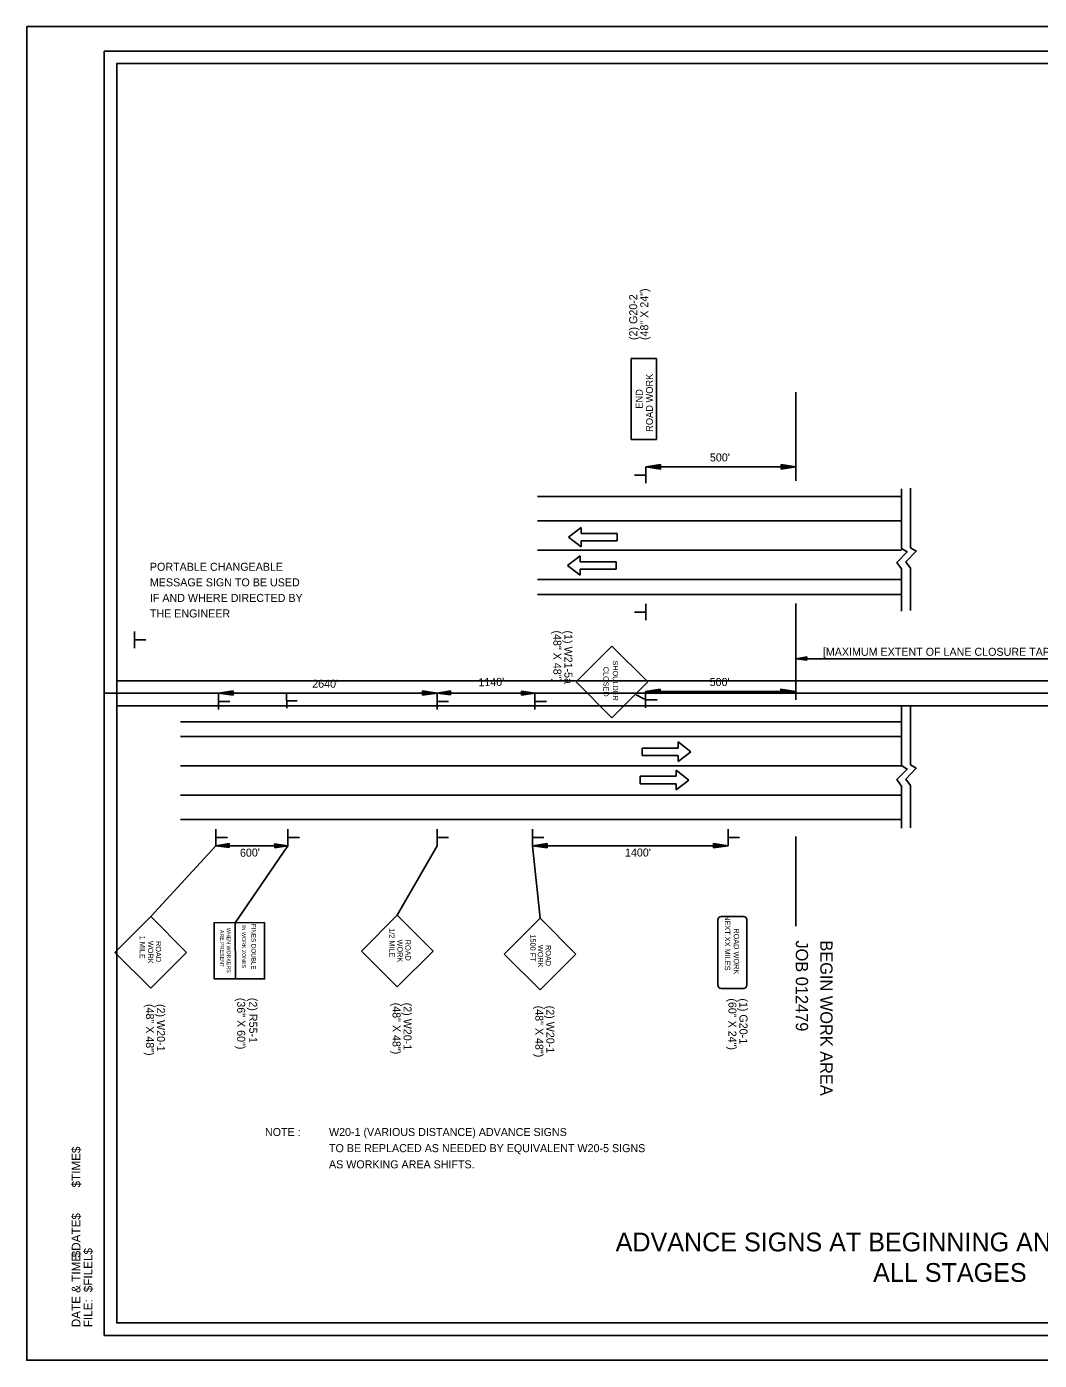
# Model space of a CAD drawing. Extents: x 1373222 to 1374279, y 380783 to 380996.
# Drawn here: x 1373222 to 1373384, y 380783.1 to 380996.5 of the extents above; entities that cross this region are included whole.
import ezdxf

# ---------------------------------------------------------------- set-up
doc = ezdxf.new("R2010")
doc.units = 0
for name, color, linetype in [('R_Border', 7, 'Continuous'), ('R_Border Notes', 7, 'Continuous'), ('R_Border Plan-Plan', 7, 'Continuous'), ('R_Draft', 7, 'Continuous'), ('R_No Plot', 7, 'Continuous')]:
    doc.layers.add(name, color=color, linetype=linetype)

msp = doc.modelspace()

# ---------------------------------------------------------------- linework, layer by layer
at = {"layer": 'R_Border'}
for p, q in [((1373234.38, 380992.59), (1373550.56, 380992.59)), ((1373234.38, 380787.13), (1373234.38, 380992.59)), ((1373234.38, 380787.13), (1373234.38, 380787.13)), ((1373550.56, 380787.13), (1373234.38, 380787.13))]:
    msp.add_line(p, q, dxfattribs=at)
at = {"layer": 'R_Border Plan-Plan'}
msp.add_line((1373234.38, 380889.86), (1373550.56, 380889.86), dxfattribs=at)
at = {"layer": 'R_Draft'}
for p, q in [((1373318.66, 380943.42), (1373318.66, 380930.43)), ((1373322.74, 380943.42), (1373318.66, 380943.42)), ((1373322.74, 380943.42), (1373322.74, 380930.43)), ((1373345.02, 380923.82), (1373345.02, 380938)), ((1373322.74, 380930.43), (1373318.66, 380930.43)), ((1373323.38, 380926.44), (1373321.03, 380926.08)), ((1373321.03, 380923.44), (1373321.03, 380926.08)), ((1373345.02, 380926.08), (1373321.03, 380926.08)), ((1373323.38, 380925.73), (1373321.03, 380926.08)), ((1373323.38, 380926.38), (1373321.42, 380926.08)), ((1373323.38, 380925.79), (1373321.42, 380926.08)), ((1373323.38, 380926.32), (1373321.83, 380926.08)), ((1373323.38, 380925.85), (1373321.83, 380926.08)), ((1373323.38, 380926.26), (1373322.22, 380926.08)), ((1373323.38, 380925.91), (1373322.22, 380926.08)), ((1373323.38, 380926.2), (1373322.61, 380926.08)), ((1373323.38, 380925.97), (1373322.61, 380926.08)), ((1373323.38, 380926.14), (1373323.01, 380926.08)), ((1373323.38, 380926.03), (1373323.01, 380926.08)), ((1373323.38, 380925.73), (1373323.38, 380926.44)), ((1373342.68, 380926.44), (1373345.02, 380926.08)), ((1373342.68, 380926.44), (1373342.68, 380925.73)), ((1373342.68, 380926.38), (1373344.63, 380926.08)), ((1373342.68, 380926.32), (1373344.23, 380926.08)), ((1373342.68, 380926.26), (1373343.84, 380926.08)), ((1373342.68, 380926.2), (1373343.44, 380926.08)), ((1373342.68, 380926.14), (1373343.05, 380926.08)), ((1373342.68, 380925.73), (1373345.02, 380926.08)), ((1373342.68, 380925.97), (1373343.44, 380926.08)), ((1373342.68, 380925.85), (1373344.23, 380926.08)), ((1373342.68, 380925.79), (1373344.63, 380926.08)), ((1373342.68, 380925.91), (1373343.84, 380926.08)), ((1373342.68, 380926.03), (1373343.05, 380926.08)), ((1373320.99, 380924.76), (1373319.19, 380924.76)), ((1373303.69, 380921.33), (1373361.91, 380921.33)), ((1373361.91, 380913.03), (1373361.91, 380922.56)), ((1373363.36, 380913.14), (1373363.36, 380922.67)), ((1373303.69, 380917.42), (1373361.91, 380917.42)), ((1373308.64, 380914.83), (1373310.67, 380916.39)), ((1373310.67, 380913.26), (1373308.64, 380914.83)), ((1373310.67, 380915.41), (1373310.67, 380916.39)), ((1373310.67, 380915.41), (1373316.43, 380915.41)), ((1373316.43, 380914.24), (1373316.43, 380915.41)), ((1373303.69, 380912.72), (1373361.91, 380912.72)), ((1373310.67, 380914.24), (1373316.43, 380914.24)), ((1373310.67, 380913.26), (1373310.67, 380914.24)), ((1373308.49, 380910.29), (1373310.52, 380911.86)), ((1373310.52, 380908.73), (1373308.49, 380910.29)), ((1373310.52, 380910.88), (1373310.52, 380911.86)), ((1373310.52, 380910.88), (1373316.28, 380910.88)), ((1373316.28, 380909.71), (1373316.28, 380910.88)), ((1373303.69, 380908.03), (1373361.91, 380908.03)), ((1373310.52, 380909.71), (1373316.28, 380909.71)), ((1373310.52, 380908.73), (1373310.52, 380909.71)), ((1373361.91, 380902.99), (1373361.91, 380909.74)), ((1373363.36, 380903.09), (1373363.36, 380909.85)), ((1373303.69, 380905.68), (1373361.91, 380905.68)), ((1373321.03, 380901.54), (1373321.03, 380904.18)), ((1373345.02, 380888.83), (1373345.02, 380904.23)), ((1373320.99, 380902.85), (1373319.19, 380902.85)), ((1373239.21, 380897.07), (1373239.21, 380899.71)), ((1373239.25, 380898.38), (1373241.05, 380898.38)), ((1373309.88, 380891.66), (1373315.61, 380897.39)), ((1373321.34, 380891.66), (1373315.61, 380897.39)), ((1373346.8, 380895.66), (1373345.02, 380895.39)), ((1373405.44, 380895.39), (1373345.02, 380895.39)), ((1373346.8, 380895.13), (1373345.02, 380895.39)), ((1373346.8, 380895.62), (1373345.32, 380895.39)), ((1373346.8, 380895.17), (1373345.32, 380895.39)), ((1373346.8, 380895.57), (1373345.63, 380895.39)), ((1373346.8, 380895.22), (1373345.63, 380895.39)), ((1373346.8, 380895.53), (1373345.92, 380895.39)), ((1373346.8, 380895.26), (1373345.92, 380895.39)), ((1373346.8, 380895.48), (1373346.23, 380895.39)), ((1373346.8, 380895.31), (1373346.23, 380895.39)), ((1373346.8, 380895.44), (1373346.52, 380895.39)), ((1373346.8, 380895.35), (1373346.52, 380895.39)), ((1373346.8, 380895.13), (1373346.8, 380895.66)), ((1373315.61, 380885.92), (1373309.88, 380891.66)), ((1373315.61, 380885.92), (1373321.34, 380891.66)), ((1373254.99, 380890.23), (1373252.64, 380889.88)), ((1373252.64, 380887.24), (1373252.64, 380889.88)), ((1373287.64, 380889.88), (1373252.64, 380889.88)), ((1373254.99, 380889.53), (1373252.64, 380889.88)), ((1373254.99, 380890.17), (1373253.03, 380889.88)), ((1373254.99, 380889.59), (1373253.03, 380889.88)), ((1373254.99, 380890.11), (1373253.44, 380889.88)), ((1373254.99, 380889.65), (1373253.44, 380889.88)), ((1373254.99, 380890.06), (1373253.83, 380889.88)), ((1373254.99, 380889.71), (1373253.83, 380889.88)), ((1373254.99, 380890), (1373254.22, 380889.88)), ((1373254.99, 380889.77), (1373254.22, 380889.88)), ((1373254.99, 380889.94), (1373254.62, 380889.88)), ((1373254.99, 380889.83), (1373254.62, 380889.88)), ((1373254.99, 380889.53), (1373254.99, 380890.23)), ((1373263.58, 380887.45), (1373263.54, 380889.85)), ((1373285.3, 380890.23), (1373287.64, 380889.88)), ((1373285.3, 380890.23), (1373285.3, 380889.53)), ((1373285.3, 380890.17), (1373287.25, 380889.88)), ((1373285.3, 380890.11), (1373286.85, 380889.88)), ((1373285.3, 380890.06), (1373286.46, 380889.88)), ((1373285.3, 380890), (1373286.06, 380889.88)), ((1373285.3, 380889.94), (1373285.67, 380889.88)), ((1373285.3, 380889.53), (1373287.64, 380889.88)), ((1373285.3, 380889.77), (1373286.06, 380889.88)), ((1373285.3, 380889.65), (1373286.85, 380889.88)), ((1373285.3, 380889.59), (1373287.25, 380889.88)), ((1373285.3, 380889.71), (1373286.46, 380889.88)), ((1373285.3, 380889.83), (1373285.67, 380889.88)), ((1373289.77, 380890.24), (1373287.64, 380889.88)), ((1373287.64, 380887.24), (1373287.64, 380889.88)), ((1373303.29, 380889.88), (1373287.64, 380889.88)), ((1373289.78, 380889.6), (1373287.64, 380889.88)), ((1373289.77, 380890.18), (1373288, 380889.89)), ((1373289.78, 380889.65), (1373288, 380889.89)), ((1373289.77, 380890.13), (1373288.37, 380889.89)), ((1373289.78, 380889.7), (1373288.37, 380889.89)), ((1373289.77, 380890.07), (1373288.72, 380889.9)), ((1373289.78, 380889.76), (1373288.72, 380889.9)), ((1373289.78, 380890.02), (1373289.08, 380889.9)), ((1373289.78, 380889.81), (1373289.08, 380889.9)), ((1373289.78, 380889.96), (1373289.44, 380889.91)), ((1373289.78, 380889.87), (1373289.44, 380889.91)), ((1373289.78, 380889.6), (1373289.77, 380890.24)), ((1373301.15, 380890.17), (1373303.29, 380889.88)), ((1373301.15, 380890.17), (1373301.16, 380889.53)), ((1373301.15, 380890.11), (1373302.93, 380889.88)), ((1373301.15, 380890.06), (1373302.57, 380889.87)), ((1373301.15, 380890.01), (1373302.21, 380889.86)), ((1373301.16, 380889.95), (1373301.85, 380889.86)), ((1373301.16, 380889.9), (1373301.49, 380889.85)), ((1373301.16, 380889.53), (1373303.29, 380889.88)), ((1373301.16, 380889.58), (1373302.93, 380889.88)), ((1373301.16, 380889.64), (1373302.57, 380889.87)), ((1373301.16, 380889.74), (1373301.85, 380889.86)), ((1373301.16, 380889.69), (1373302.21, 380889.86)), ((1373301.16, 380889.8), (1373301.49, 380889.85)), ((1373303.29, 380887.24), (1373303.29, 380889.88)), ((1373320.82, 380888.92), (1373319.47, 380889.61)), ((1373323.34, 380890.51), (1373320.99, 380890.16)), ((1373320.99, 380887.52), (1373320.99, 380890.16)), ((1373344.99, 380890.16), (1373320.99, 380890.16)), ((1373323.34, 380889.81), (1373320.99, 380890.16)), ((1373321.03, 380888.83), (1373322.83, 380888.83)), ((1373323.34, 380890.45), (1373321.38, 380890.16)), ((1373323.34, 380889.87), (1373321.38, 380890.16)), ((1373323.34, 380890.39), (1373321.79, 380890.16)), ((1373323.34, 380889.93), (1373321.79, 380890.16)), ((1373323.34, 380890.33), (1373322.18, 380890.16)), ((1373323.34, 380889.99), (1373322.18, 380890.16)), ((1373323.34, 380890.28), (1373322.58, 380890.16)), ((1373323.34, 380890.05), (1373322.58, 380890.16)), ((1373323.34, 380890.22), (1373322.97, 380890.16)), ((1373323.34, 380890.11), (1373322.97, 380890.16)), ((1373323.34, 380889.81), (1373323.34, 380890.51)), ((1373342.64, 380890.51), (1373344.99, 380890.16)), ((1373342.64, 380890.51), (1373342.64, 380889.81)), ((1373342.64, 380890.45), (1373344.59, 380890.16)), ((1373342.64, 380890.39), (1373344.19, 380890.16)), ((1373342.64, 380890.33), (1373343.8, 380890.16)), ((1373342.64, 380890.27), (1373343.4, 380890.16)), ((1373342.64, 380890.22), (1373343.01, 380890.16)), ((1373342.64, 380889.81), (1373344.99, 380890.16)), ((1373342.64, 380890.04), (1373343.4, 380890.16)), ((1373342.64, 380889.93), (1373344.19, 380890.16)), ((1373342.64, 380889.87), (1373344.59, 380890.16)), ((1373342.64, 380889.99), (1373343.8, 380890.16)), ((1373342.64, 380890.11), (1373343.01, 380890.16)), ((1373252.68, 380888.55), (1373254.48, 380888.55)), ((1373263.6, 380888.64), (1373265.23, 380888.67)), ((1373287.68, 380888.55), (1373289.48, 380888.55)), ((1373303.33, 380888.55), (1373305.13, 380888.55)), ((1373361.91, 380878.3), (1373361.91, 380887.82)), ((1373363.36, 380878.4), (1373363.36, 380887.92)), ((1373246.61, 380885.31), (1373342.65, 380885.31)), ((1373342.65, 380885.31), (1373361.91, 380885.31)), ((1373246.61, 380882.96), (1373342.65, 380882.96)), ((1373342.65, 380882.96), (1373361.91, 380882.96)), ((1373326.18, 380881.1), (1373320.43, 380881.1)), ((1373320.43, 380881.1), (1373320.43, 380879.92)), ((1373326.18, 380882.08), (1373326.18, 380881.1)), ((1373326.18, 380882.08), (1373328.21, 380880.51)), ((1373328.21, 380880.51), (1373326.18, 380878.95)), ((1373246.61, 380878.26), (1373342.65, 380878.26)), ((1373326.18, 380879.92), (1373320.43, 380879.92)), ((1373326.18, 380879.92), (1373326.18, 380878.95)), ((1373342.65, 380878.26), (1373361.96, 380878.26)), ((1373325.88, 380876.57), (1373320.13, 380876.57)), ((1373320.13, 380876.57), (1373320.13, 380875.39)), ((1373325.88, 380877.54), (1373325.88, 380876.57)), ((1373325.88, 380877.54), (1373327.91, 380875.98)), ((1373327.91, 380875.98), (1373325.88, 380874.41)), ((1373325.88, 380875.39), (1373320.13, 380875.39)), ((1373325.88, 380875.39), (1373325.88, 380874.41)), ((1373361.91, 380868.25), (1373361.91, 380875)), ((1373363.36, 380868.35), (1373363.36, 380875.11)), ((1373246.61, 380873.57), (1373342.65, 380873.57)), ((1373342.65, 380873.57), (1373361.91, 380873.57)), ((1373246.61, 380869.66), (1373342.65, 380869.66)), ((1373342.65, 380869.66), (1373361.91, 380869.66)), ((1373252.24, 380865.47), (1373252.24, 380868.11)), ((1373263.78, 380865.47), (1373263.78, 380868.11)), ((1373287.64, 380865.47), (1373287.64, 380868.11)), ((1373302.89, 380865.47), (1373302.89, 380868.11)), ((1373334.19, 380865.47), (1373334.19, 380868.11)), ((1373252.24, 380865.47), (1373241.82, 380854.14)), ((1373254.37, 380865.83), (1373252.24, 380865.47)), ((1373263.78, 380865.47), (1373252.24, 380865.47)), ((1373254.38, 380865.19), (1373252.24, 380865.47)), ((1373252.28, 380866.79), (1373254.08, 380866.79)), ((1373254.37, 380865.77), (1373252.6, 380865.48)), ((1373254.38, 380865.24), (1373252.6, 380865.48)), ((1373254.37, 380865.72), (1373252.97, 380865.48)), ((1373254.38, 380865.29), (1373252.97, 380865.48)), ((1373254.37, 380865.67), (1373253.32, 380865.49)), ((1373254.38, 380865.35), (1373253.32, 380865.49)), ((1373254.37, 380865.61), (1373253.68, 380865.5)), ((1373254.38, 380865.4), (1373253.68, 380865.5)), ((1373254.38, 380865.56), (1373254.04, 380865.5)), ((1373254.38, 380865.46), (1373254.04, 380865.5)), ((1373254.38, 380865.19), (1373254.37, 380865.83)), ((1373263.78, 380865.47), (1373255.35, 380853.15)), ((1373261.64, 380865.76), (1373263.78, 380865.47)), ((1373261.64, 380865.76), (1373261.65, 380865.12)), ((1373261.64, 380865.7), (1373263.42, 380865.47)), ((1373261.64, 380865.65), (1373263.05, 380865.46)), ((1373261.64, 380865.6), (1373262.7, 380865.45)), ((1373261.64, 380865.54), (1373262.34, 380865.45)), ((1373261.64, 380865.49), (1373261.98, 380865.44)), ((1373261.64, 380865.33), (1373262.34, 380865.45)), ((1373261.64, 380865.39), (1373261.98, 380865.44)), ((1373261.65, 380865.12), (1373263.78, 380865.47)), ((1373261.65, 380865.17), (1373263.42, 380865.47)), ((1373261.65, 380865.23), (1373263.05, 380865.46)), ((1373261.65, 380865.28), (1373262.7, 380865.45)), ((1373263.81, 380866.79), (1373265.62, 380866.79)), ((1373287.64, 380865.47), (1373281.27, 380854.35)), ((1373287.68, 380866.79), (1373289.48, 380866.79)), ((1373305.24, 380865.82), (1373302.89, 380865.47)), ((1373302.89, 380865.47), (1373304.11, 380853.87)), ((1373334.19, 380865.47), (1373302.89, 380865.47)), ((1373305.24, 380865.12), (1373302.89, 380865.47)), ((1373302.93, 380866.79), (1373304.73, 380866.79)), ((1373305.24, 380865.77), (1373303.28, 380865.47)), ((1373305.24, 380865.18), (1373303.28, 380865.47)), ((1373305.24, 380865.71), (1373303.69, 380865.47)), ((1373305.24, 380865.24), (1373303.69, 380865.47)), ((1373305.24, 380865.65), (1373304.08, 380865.47)), ((1373305.24, 380865.3), (1373304.08, 380865.47)), ((1373305.24, 380865.59), (1373304.48, 380865.47)), ((1373305.24, 380865.36), (1373304.48, 380865.47)), ((1373305.24, 380865.53), (1373304.87, 380865.47)), ((1373305.24, 380865.42), (1373304.87, 380865.47)), ((1373305.24, 380865.12), (1373305.24, 380865.82)), ((1373331.84, 380865.82), (1373334.19, 380865.47)), ((1373331.84, 380865.82), (1373331.84, 380865.12)), ((1373331.84, 380865.77), (1373333.79, 380865.47)), ((1373331.84, 380865.71), (1373333.39, 380865.47)), ((1373331.84, 380865.65), (1373333, 380865.47)), ((1373331.84, 380865.59), (1373332.6, 380865.47)), ((1373331.84, 380865.53), (1373332.21, 380865.47)), ((1373331.84, 380865.12), (1373334.19, 380865.47)), ((1373331.84, 380865.36), (1373332.6, 380865.47)), ((1373331.84, 380865.24), (1373333.39, 380865.47)), ((1373331.84, 380865.18), (1373333.79, 380865.47)), ((1373331.84, 380865.3), (1373333, 380865.47)), ((1373331.84, 380865.42), (1373332.21, 380865.47)), ((1373334.22, 380866.79), (1373336.03, 380866.79)), ((1373345.02, 380866.93), (1373345.02, 380852.62)), ((1373236.09, 380848.41), (1373241.82, 380854.14)), ((1373247.55, 380848.41), (1373241.82, 380854.14)), ((1373255.36, 380844.15), (1373255.35, 380853.15)), ((1373275.54, 380848.61), (1373281.27, 380854.35)), ((1373287, 380848.61), (1373281.27, 380854.35)), ((1373298.38, 380848.14), (1373304.11, 380853.87)), ((1373309.85, 380848.14), (1373304.11, 380853.87)), ((1373332.57, 380843.16), (1373332.57, 380853.64)), ((1373333.08, 380854.14), (1373336.68, 380854.14)), ((1373337.19, 380843.16), (1373337.19, 380853.64)), ((1373241.82, 380842.67), (1373236.09, 380848.41)), ((1373241.82, 380842.67), (1373247.55, 380848.41)), ((1373281.27, 380842.88), (1373275.54, 380848.61)), ((1373281.27, 380842.88), (1373287, 380848.61)), ((1373304.11, 380842.41), (1373298.38, 380848.14)), ((1373304.11, 380842.41), (1373309.85, 380848.14)), ((1373333.08, 380842.65), (1373336.68, 380842.65))]:
    msp.add_line(p, q, dxfattribs=at)
for points in [[(1373361.91, 380913.03), (1373362.84, 380912.48), (1373361.19, 380910.78), (1373361.91, 380909.74)], [(1373363.36, 380913.14), (1373364.28, 380912.59), (1373362.63, 380910.88), (1373363.36, 380909.85)], [(1373361.91, 380878.3), (1373362.84, 380877.74), (1373361.19, 380876.04), (1373361.91, 380875)], [(1373363.36, 380878.4), (1373364.28, 380877.85), (1373362.63, 380876.14), (1373363.36, 380875.11)]]:
    msp.add_lwpolyline(points, dxfattribs=at)
msp.add_lwpolyline([(1373260.02, 380853.16), (1373251.97, 380853.15), (1373251.98, 380844.15), (1373260.03, 380844.15)], close=True, dxfattribs=at)
for centre, start, end in [((1373333.08, 380853.64), 90, 180), ((1373336.68, 380853.64), 360, 90), ((1373333.08, 380843.16), 180, 270), ((1373336.68, 380843.16), 270, 0)]:
    msp.add_arc(centre, 0.505, start, end, dxfattribs=at)
at = {"layer": 'R_No Plot'}
for points in [[(1373221.98, 380996.49), (1373555.32, 380996.49), (1373555.32, 380783.15), (1373221.98, 380783.15)], [(1373548.56, 380891.86), (1373236.38, 380891.86), (1373236.38, 380990.59), (1373485.92, 380990.59), (1373485.92, 380980.71), (1373503.46, 380980.71), (1373527.56, 380980.71), (1373527.56, 380958.38), (1373548.56, 380958.38)], [(1373236.38, 380990.59), (1373485.92, 380990.59), (1373485.92, 380980.71), (1373503.46, 380980.71), (1373527.56, 380980.71), (1373527.56, 380958.38), (1373548.56, 380958.38), (1373548.56, 380789.13), (1373236.38, 380789.13)], [(1373236.38, 380887.86), (1373548.56, 380887.86), (1373548.56, 380789.13), (1373236.38, 380789.13)]]:
    msp.add_lwpolyline(points, close=True, dxfattribs=at)

# ---------------------------------------------------------------- texts
at = {"layer": 'R_Border Notes'}
for s, height, p in [('$TIME$', 1.397, (1373230.58, 380810.8)), ('$DATE$', 1.397, (1373230.58, 380799.63)), ('DATE & TIME:', 1.3968, (1373230.58, 380788.45)), ('$FILEL$', 1.397, (1373232.5, 380794.04)), ('FILE: ', 1.397, (1373232.5, 380788.45))]:
    msp.add_text(s, height=height, rotation=90, dxfattribs=at).set_placement(p)
at = {"layer": 'R_Draft'}
for s, height, rotation, p in [('(2) G20-2', 1.28, 90, (1373319.65, 380946.36)), ('(48" X 24")', 1.28, 90, (1373321.41, 380946.36)), ('ROAD WORK', 1.109, 90, (1373322.16, 380931.67)), ('END', 1.109, 90, (1373320.52, 380935.38)), ('(48" X 48")', 1.28, 270, (1373306.24, 380899.9)), ('(1) W21-5a', 1.28, 270, (1373308, 380899.9)), ('CLOSED', 0.84, 270.0004, (1373314.25, 380894.09)), ('SHOULDER', 0.84, 270, (1373315.75, 380895.1)), ("1140'", 1.28, 1.2304, (1373294.25, 380890.97)), ("600'", 1.28, 1.2304, (1373256.11, 380863.69)), ('IN WORK ZONES', 0.6113, 270.0501, (1373256.42, 380852.74)), ('FINES DOUBLE', 0.72, 270.0501, (1373257.92, 380852.96)), (' NEXT XX MILES', 0.8486, 270, (1373333.67, 380854.68)), ('1 MILE', 0.845, 270.0004, (1373240.07, 380851.08)), ('ARE PRESENT', 0.6114, 270.0501, (1373252.92, 380852)), ('WHEN WORKERS', 0.6114, 270.0501, (1373253.99, 380852.32)), ('1/2 MILE', 0.845, 270, (1373280.01, 380852.27)), ('WORK', 0.845, 270, (1373281.29, 380850.45)), ('ROAD', 0.845, 270.0004, (1373282.56, 380850.43)), ('1500 FT', 0.845, 270.0004, (1373302.55, 380851.27)), ('ROAD WORK', 0.848, 270, (1373335.1, 380852.25)), ('WORK', 0.845, 270, (1373241.37, 380850.24)), ('ROAD', 0.845, 270.0004, (1373242.64, 380850.22)), ('WORK', 0.845, 270, (1373303.75, 380849.61)), ('ROAD', 0.845, 270.0004, (1373305.02, 380849.59)), ('JOB 012479', 1.956, 270, (1373345.02, 380850.32)), ('BEGIN WORK AREA', 1.9558, 270, (1373348.94, 380850.32)), ('(48" X 48")', 1.28, 270, (1373241.06, 380840.15)), ('(2) W20-1', 1.28, 270, (1373242.82, 380840.15)), ('(36" X 60")', 1.2802, 270.0501, (1373255.65, 380841.14)), ('(2) R55-1', 1.28, 270.0501, (1373257.57, 380841.14)), ('(48" X 48")', 1.28, 270, (1373280.51, 380840.36)), ('(2) W20-1', 1.28, 270, (1373282.27, 380840.36)), ('(48" X 48")', 1.28, 270, (1373303.35, 380839.88)), ('(2) W20-1', 1.28, 270, (1373305.11, 380839.88)), ('(60" X 24")', 1.28, 270, (1373334.24, 380841.05)), ('(1) G20-1', 1.28, 270, (1373336.01, 380841.05))]:
    msp.add_text(s, height=height, rotation=rotation, dxfattribs=at).set_placement(p)
for s, height, p in [("500'", 1.28, (1373331.28, 380926.94)), ('PORTABLE CHANGEABLE', 1.28, (1373241.69, 380909.45)), ('MESSAGE SIGN TO BE USED', 1.28, (1373241.69, 380906.96)), ('IF AND WHERE DIRECTED BY', 1.28, (1373241.69, 380904.47)), ('THE ENGINEER', 1.28, (1373241.69, 380901.98)), ('[MAXIMUM EXTENT OF LANE CLOSURE TAPERS]', 1.28, (1373349.35, 380895.85)), ("2640'", 1.28, (1373267.66, 380890.75)), ("500'", 1.28, (1373331.24, 380891.02)), ("1400'", 1.28, (1373317.69, 380863.74)), ('NOTE :', 1.28, (1373260.1, 380819.03)), ('W20-1 (VARIOUS DISTANCE) ADVANCE SIGNS', 1.28, (1373270.34, 380819.03)), ('TO BE REPLACED AS NEEDED BY EQUIVALENT W20-5 SIGNS', 1.28, (1373270.34, 380816.45)), ('AS WORKING AREA SHIFTS.', 1.28, (1373270.34, 380813.86)), ('ADVANCE SIGNS AT BEGINNING AND END OF JOB', 3.0041, (1373316.2, 380800.58)), ('ALL STAGES', 3.004, (1373357.39, 380795.7))]:
    msp.add_text(s, height=height, dxfattribs=at).set_placement(p)

doc.saveas('drawing.dxf')
